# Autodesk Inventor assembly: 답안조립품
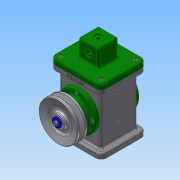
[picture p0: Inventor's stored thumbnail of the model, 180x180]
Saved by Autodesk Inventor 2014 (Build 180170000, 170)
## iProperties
Created: 2017-08
Part Number: 답안조립품
Document SubType Name: Assembly
Designer: oa51
Author: oa51
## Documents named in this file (18)
- C:\Users\oa51\Desktop\470808V1020\답안조립품.iam
- C:\Users\oa51\Desktop\470808V1020\본체.ipt
- C:\Users\oa51\Desktop\470808V1020\E-링.ipt
- C:\Users\oa51\Desktop\470808V1020\V-벨트풀리.ipt
- C:\Users\oa51\Desktop\470808V1020\덮개.ipt
- C:\Users\oa51\Desktop\470808V1020\뒤커버.ipt
- C:\Users\oa51\Desktop\470808V1020\링크.ipt
- C:\Users\oa51\Desktop\470808V1020\베어링 17 x 40 x 12.ipt
- C:\Users\oa51\Desktop\470808V1020\볼트 M4 x 8.ipt
- C:\Users\oa51\Desktop\470808V1020\볼트 M4 x 10.ipt
- C:\Users\oa51\Desktop\470808V1020\슬라이더.ipt
- C:\Users\oa51\Desktop\470808V1020\앞커버.ipt
- C:\Users\oa51\Desktop\470808V1020\오일 실 17 30 8.ipt
- C:\Users\oa51\Desktop\470808V1020\와셔 4x16.ipt
- C:\Users\oa51\Desktop\470808V1020\클레비스 핀 6 x 22.ipt
- 클레비스 핀 6 x 22.ipt
- C:\Users\oa51\Desktop\470808V1020\키 4 x 4 x 12.ipt
- C:\Users\oa51\Desktop\470808V1020\편심축.ipt
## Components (2 placed, 2 different names)
1. E-링:1 — 각도:3
2. V-벨트풀리:1 — 각도:2
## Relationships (2: Angle 2)
- 각도:2 [Angle]: V-벨트풀리:1
- 각도:3 [Angle]: E-링:1
